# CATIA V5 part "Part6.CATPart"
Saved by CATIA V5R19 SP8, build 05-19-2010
Part number: Support
Bounding box of the stored display mesh (mm): x -43.972 to 43.972, y -280 to 500, z -42.517 to 39.875
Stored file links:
  G:\EU_thinkMotion\CFAO_2010\MMS_groupe1\MMS_groupe1\OK\ppiault\piault\piault_cfao\Part6.CATPart
  G:\EU_thinkMotion\CFAO_2010\MMS_groupe1\MMS_groupe1\OK\ppiault\piault\piault_cfao\Part2.CATPart
  D:\Catia\Finaltest.CATProduct
  G:\Catia Projet\CFAO2\Product2.CATProduct
  G:\EU_thinkMotion\CFAO_2010\MMS_groupe1\MMS_groupe1\OK\ppiault\piault\piault_cfao\Part1.CATPart
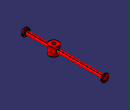
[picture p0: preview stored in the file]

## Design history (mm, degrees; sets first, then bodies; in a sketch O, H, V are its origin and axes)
Parameters
  z0 = 0 mm
  y0 = 0 mm
  z0p = 0 mm
  y0p = -280 mm
  rayon_axe = 16 mm
  rayon_bielle = 18 mm
External parameters (linked from other documents)
  External.DiametreRabatteur = 400 mm
  External.Longueur_Support = 280 mm
Set1
  Line1: linked copy from another document
Set2
  Point1: (0, 0 {= y0}, 0 {= z0})
  Point2: (0, -280 {= y0p}, 0 {= z0p})
Body1 (main body)
  Sketch1 on yz-plane, origin (0, 0, 0), H (0, 1, 0), V (0, 0, 1)
    line L1 (-15, 39.8747) -> (-44.0037, 39.8747)
    line L2 (-44.0037, 39.8747) -> (-44.0037, -42.5165)
    line L3 (-44.0037, -42.5165) -> (-15, -42.5165)
    line L4 (-15, -42.5165) -> (-15, 39.8747)
    horizontal: L1 H, L3 H
    vertical: L2 V, L4 V
  Shaft1: profile Sketch1, axis Line1, angle 360
  Sketch2 on yz-plane, origin (0, 0, 0), H (0, 1, 0), V (0, 0, 1)
    line L1 (17, 18) -> (490, 18)
    line L2 (500, 22.8223) -> (500, 0)
    line L3 (500, 0) -> (17, 0)
    line L4 (17, 0) -> (17, 18)
    line L5 (-262.0905, 18) -> (-15, 18)
    line L6 (-15, 18) -> (-15, 0)
    line L7 (-15, 0) -> (-262.0905, 0)
    line L8 (-280, 36) -> (-262.0905, 36)
    line L9 (-262.0905, 36) -> (-262.0905, 18)
    line L10 (-262.0905, 0) -> (-280, 0)
    line L11 (-280, 0) -> (-280, 36)
    reference projected line E1 (-15, -42.5165) -> (-15, 39.8747) from Sketch1.L4
    line L12 (490, 36) -> (500, 36)
    line L13 (500, 36) -> (500, 22.8223)
    line L14 (490, 36) -> (490, 18)
    distance L5 L7 = 18 {= rayon_bielle}
    distance L1 L3 = 18 {= rayon_bielle}
    distance L8 L10 = 36 {= rayon_bielle *2}
    distance L4 L6 = 32 {= rayon_axe *2}
    distance L2 V = 500 {= External.DiametreRabatteur  +100mm}
    distance L12 L3 = 36 {= rayon_bielle *2}
    distance V L11 = 280 {= External.Longueur_Support}
    distance L14 L2 = 10
    horizontal: L1 H, L3 H, L5 H, L7 H, L8 H, L10 H, L12 H
    vertical: L2 V, L4 V, L6 V, L9 V, L11 V, L14 V, L13 V
    coincidence: E1 L6
  Shaft2: profile Sketch2, axis Sketch2.L3, angle 360
  Fillet1: radius 5, on edge [face of Shaft1 from Sketch1.L2 | face of Shaft2 from Sketch2.L1]; edge [face of Shaft2 from Sketch2.L5 | face of Shaft1 from Sketch1.L2]
  Fillet2: radius 5, on edge [face of Shaft2 from Sketch2.L1 | face of Shaft2 from Sketch2.L14]; edge [face of Shaft2 from Sketch2.L14 | face of Shaft2 from Sketch2.L12]
  Fillet3: radius 5, on edge [face of Shaft2 from Sketch2.L8 | face of Shaft2 from Sketch2.L9]; edge [face of Shaft2 from Sketch2.L9 | face of Shaft2 from Sketch2.L5]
